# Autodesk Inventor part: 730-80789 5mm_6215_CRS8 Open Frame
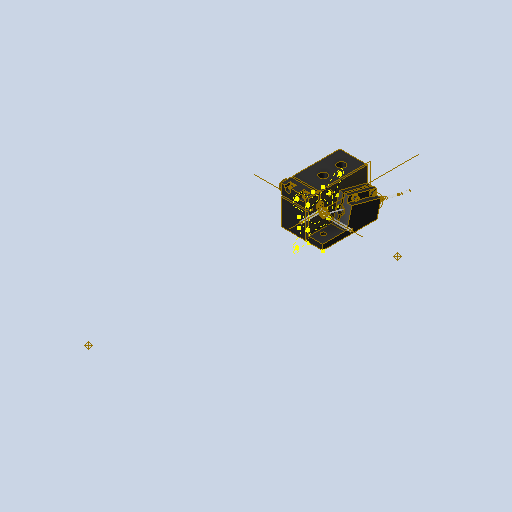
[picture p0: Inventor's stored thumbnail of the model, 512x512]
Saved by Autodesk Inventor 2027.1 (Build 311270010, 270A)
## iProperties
Created: 2014-04
Part Number: 730-80789 5mm_6215_CRS8 Open Frame
Material: Generic
Description: STEP AP203
Document SubType Name: Modeling
Designer: Radek
Density: 1 g/cm^3
Appearance: Default
Sending System: SolidWorks 2011
Preprocessor: SwSTEP 2.0
Title: 730-80789 4mm_6215_CRS8 Open Frame.STEP
Revision Number: ANY
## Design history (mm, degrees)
feature "Composite1"
sketch "Sketch1"
  geometry: 5 further points
  constraints: 1 vertical alignment, 1 other
workaxis "Work Axis1"
workaxis "Work Axis2"
workplane "Work Plane1"
workpoint "Work Point1"
workpoint "Work Point2"
workaxis "Work Axis3"
workaxis "Work Axis4"
sketch "Sketch4"
  geometry: C1 r 2 at (0, 0) reference; 1 further point
extrude "Extrusion1" new body sketch "Sketch4" distance "d1" = 65; taper "d2" = 0 deg
sketch "Sketch5"
  geometry: C1 r 2 at (0, 0) reference; 1 further point
extrude "Extrusion2" join sketch "Sketch5" distance "d3" = 300; taper "d4" = 0 deg
workpoint "Work Point3"
workplane "Work Plane2"
  workpoint "Work Point4"
workplane "Work Plane3"
body "Solid1"
node "Finishes"
sketch "Sketch3"
  geometry: L1 (9.561, -28.496)-(22.687, -41.622) reference; L2 (22.687, -41.622)-(30.815, -41.622) reference; L3 (30.815, -41.622)-(33.355, -39.082) reference; L4 (33.355, -30.954)-(33.355, -39.082) reference; L5 (20.229, -17.828)-(33.355, -30.954) reference; L6 (18.369, 0.706)-(18.369, -13.337) reference; L7 (20.229, 5.196)-(33.355, 18.322) reference; L8 (33.355, 26.45)-(33.355, 18.322) reference; L9 (30.815, 28.99)-(33.355, 26.45) reference; L10 (22.687, 28.99)-(30.815, 28.99) reference; L11 (9.561, 15.864)-(22.687, 28.99) reference; L12 (-8.973, 14.004)-(5.071, 14.004) reference; L13 (-13.463, 15.864)-(-26.589, 28.99) reference; L14 (-34.717, 28.99)-(-26.589, 28.99) reference; L15 (-34.717, 28.99)-(-37.257, 26.45) reference; L16 (-37.257, 26.45)-(-37.257, 18.322) reference; L17 (-24.131, 5.196)-(-37.257, 18.322) reference; L18 (-22.271, 0.706)-(-22.271, -13.337) reference; L19 (-24.131, -17.828)-(-37.257, -30.954) reference; L20 (-37.257, -30.954)-(-37.257, -39.082) reference; L21 (-37.257, -39.082)-(-34.717, -41.622) reference; L22 (-34.717, -41.622)-(-26.589, -41.622) reference; L23 (-13.463, -28.496)-(-26.589, -41.622) reference; L24 (-8.973, -26.636)-(5.071, -26.636) reference; C1 r 3.264 at (28.049, 23.684) reference; C2 r 3.264 at (13.049, 8.684) reference; C3 r 3.264 at (-16.951, 8.684) reference; C4 r 3.264 at (-31.951, 23.684) reference; C5 r 3.264 at (-31.951, -36.316) reference; C6 r 3.264 at (-16.951, -21.316) reference; C7 r 3.264 at (13.049, -21.316) reference; C8 r 3.264 at (28.049, -36.316) reference; C9 r 13.398 at (-1.951, -6.316) reference; A1 r 6.35 centre (24.719, -13.337) between (18.369, -13.337) and (20.229, -17.828) reference; A2 r 6.35 centre (24.719, 0.706) between (20.229, 5.196) and (18.369, 0.706) reference; A3 r 6.35 centre (5.071, 20.354) between (5.071, 14.004) and (9.561, 15.864) reference; A4 r 6.35 centre (-8.973, 20.354) between (-13.463, 15.864) and (-8.973, 14.004) reference; A5 r 6.35 centre (-28.621, 0.706) between (-22.271, 0.706) and (-24.131, 5.196) reference; A6 r 6.35 centre (-28.621, -13.337) between (-24.131, -17.828) and (-22.271, -13.337) reference; A7 r 6.35 centre (-8.973, -32.986) between (-8.973, -26.636) and (-13.463, -28.496) reference; A8 r 6.35 centre (5.071, -32.986) between (9.561, -28.496) and (5.071, -26.636) reference; 1 further point
node "Reference1"
body "Srf1"
node "Finish1" dims "Finish1_Area" = 923.28975
other parameters: "d0" = 0
